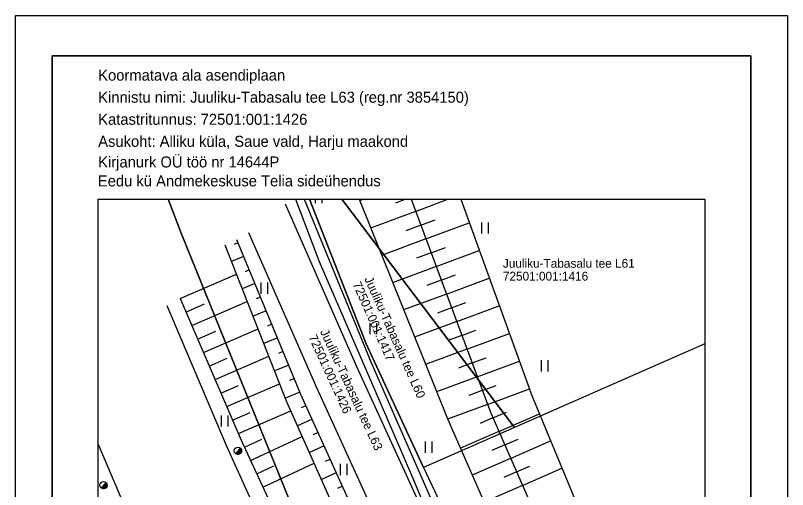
# Model space of a CAD drawing. Extents: x 533290.5 to 533343, y 6581488.2 to 6581562.4.
# Drawn here: x 533290.5 to 533343, y 6581530.2 to 6581562.4 of the extents above; entities that cross this region are included whole.
import ezdxf

# ---------------------------------------------------------------- set-up
doc = ezdxf.new("R2010")
doc.units = 0
for name, color, linetype in [('HALJASTUS', 7, 'Continuous'), ('MPKAABEL', 7, 'Continuous'), ('PIIR', 7, 'Continuous'), ('POST', 7, 'Continuous'), ('RELJEEF', 7, 'Continuous'), ('SITRASS', 7, 'Continuous'), ('TEE', 7, 'Continuous'), ('VORMISTUS', 7, 'Continuous')]:
    doc.layers.add(name, color=color, linetype=linetype)

msp = doc.modelspace()

# ---------------------------------------------------------------- linework, layer by layer
at = {"layer": 'HALJASTUS'}
for p, q in [((533310.914, 6581549.925), (533310.914, 6581549.665)), ((533311.369, 6581549.925), (533311.369, 6581549.665)), ((533322.224, 6581548.356), (533322.224, 6581547.595)), ((533322.679, 6581548.356), (533322.679, 6581547.595)), ((533307.211, 6581544.271), (533307.211, 6581543.51)), ((533307.666, 6581544.271), (533307.666, 6581543.51)), ((533314.628, 6581541.515), (533314.628, 6581540.754)), ((533315.083, 6581541.515), (533315.083, 6581540.754)), ((533326.275, 6581538.982), (533326.275, 6581538.221)), ((533326.73, 6581538.982), (533326.73, 6581538.221)), ((533304.51, 6581535.234), (533304.51, 6581534.473)), ((533304.966, 6581535.234), (533304.966, 6581534.473)), ((533318.384, 6581533.45), (533318.384, 6581532.689)), ((533318.839, 6581533.45), (533318.839, 6581532.689)), ((533312.613, 6581531.94), (533312.613, 6581531.179)), ((533313.068, 6581531.94), (533313.068, 6581531.179))]:
    msp.add_line(p, q, dxfattribs=at)
at = {"layer": 'MPKAABEL'}
msp.add_lwpolyline([(533309.585, 6581549.925), (533311.184, 6581545.697), (533315.768, 6581535.104), (533317.532, 6581531.021), (533318.413, 6581528.914), (533322.317, 6581520.59), (533323.335, 6581518.773), (533327.821, 6581509.555), (533328.223, 6581508.944), (533328.79, 6581508.605), (533328.705, 6581507.998), (533329.72, 6581506.331), (533333.034, 6581500.482)], dxfattribs=at)
at = {"layer": 'PIIR'}
for points in [[(533324.524, 6581497.425), (533319, 6581507.54), (533311.52, 6581523.65), (533301.8, 6581547.63), (533300.925, 6581549.925)], [(533300.925, 6581549.925), (533301.8, 6581547.63), (533311.52, 6581523.65), (533319, 6581507.54), (533324.524, 6581497.425)], [(533312.733, 6581549.925), (533324.47, 6581534.41), (533318.28, 6581531.69), (533314.39, 6581540.11), (533310.517, 6581549.925)], [(533310.517, 6581549.925), (533314.39, 6581540.11), (533318.28, 6581531.69), (533326.26, 6581514.77), (533336.001, 6581497.425)], [(533337.407, 6581540.101), (533324.47, 6581534.41), (533312.733, 6581549.925)], [(533337.407, 6581540.101), (533324.47, 6581534.41), (533318.28, 6581531.69), (533326.26, 6581514.77), (533336.001, 6581497.425)]]:
    msp.add_lwpolyline(points, dxfattribs=at)
at = {"layer": 'POST'}
for p, q in [((533305.487, 6581532.643), (533305.84, 6581532.997)), ((533296.35, 6581530.309), (533296.704, 6581530.663))]:
    msp.add_line(p, q, dxfattribs=at)
for centre in [(533305.664, 6581532.82), (533296.527, 6581530.486)]:
    msp.add_circle(centre, 0.25, dxfattribs=at)
for centre, radius, start, end in [((533305.664, 6581532.82), 0.225, 224.8541, 45.0356), ((533305.664, 6581532.82), 0.2, 224.8427, 45.047), ((533305.664, 6581532.82), 0.175, 224.8281, 45.0616), ((533305.664, 6581532.82), 0.15, 224.8087, 45.081), ((533305.664, 6581532.82), 0.125, 224.7814, 45.1083), ((533305.664, 6581532.82), 0.1, 224.7406, 45.1491), ((533305.664, 6581532.82), 0.075, 224.6725, 45.2172), ((533305.664, 6581532.82), 0.05, 224.5363, 45.3534), ((533305.664, 6581532.82), 0.025, 224.1278, 45.7619), ((533296.527, 6581530.486), 0.225, 224.8541, 45.0356), ((533296.527, 6581530.486), 0.2, 224.8427, 45.047), ((533296.527, 6581530.486), 0.175, 224.8281, 45.0616), ((533296.527, 6581530.486), 0.15, 224.8087, 45.081), ((533296.527, 6581530.486), 0.125, 224.7814, 45.1083), ((533296.527, 6581530.486), 0.1, 224.7406, 45.1491), ((533296.527, 6581530.486), 0.075, 224.6725, 45.2172), ((533296.527, 6581530.486), 0.05, 224.5363, 45.3534), ((533296.527, 6581530.486), 0.025, 224.1278, 45.7619)]:
    msp.add_arc(centre, radius, start, end, dxfattribs=at)
at = {"layer": 'RELJEEF'}
for p, q in [((533314.207, 6581549.925), (533313.935, 6581549.824)), ((533317.074, 6581549.925), (533316.367, 6581549.662)), ((533317.744, 6581549.107), (533319.942, 6581549.925)), ((533317.744, 6581549.107), (533314.683, 6581547.968)), ((533318.093, 6581548.17), (533317.081, 6581547.793)), ((533318.093, 6581548.17), (533319.079, 6581548.537)), ((533318.442, 6581547.233), (533321.391, 6581548.33)), ((533318.442, 6581547.233), (533315.43, 6581546.112)), ((533305.664, 6581546.968), (533305.395, 6581546.856)), ((533318.79, 6581546.296), (533319.771, 6581546.66)), ((533306.047, 6581546.044), (533305.223, 6581545.702)), ((533318.79, 6581546.296), (533317.795, 6581545.925)), ((533319.139, 6581545.358), (533322.072, 6581546.449)), ((533306.43, 6581545.12), (533306.15, 6581545.004)), ((533319.139, 6581545.358), (533316.178, 6581544.257)), ((533301.723, 6581543.178), (533305.563, 6581544.838)), ((533319.488, 6581544.421), (533318.509, 6581544.057)), ((533319.488, 6581544.421), (533320.463, 6581544.784)), ((533319.837, 6581543.484), (533322.753, 6581544.569)), ((533306.813, 6581544.197), (533305.955, 6581543.841)), ((533319.837, 6581543.484), (533316.925, 6581542.401)), ((533302.12, 6581542.26), (533303.39, 6581542.809)), ((533302.517, 6581541.343), (533306.295, 6581542.976)), ((533307.196, 6581543.273), (533306.905, 6581543.152)), ((533320.185, 6581542.547), (533321.155, 6581542.907)), ((533307.579, 6581542.349), (533306.687, 6581541.979)), ((533320.185, 6581542.547), (533319.223, 6581542.189)), ((533320.534, 6581541.609), (533323.434, 6581542.688)), ((533307.963, 6581541.426), (533307.66, 6581541.3)), ((533320.534, 6581541.609), (533317.673, 6581540.545)), ((533302.914, 6581540.425), (533304.163, 6581540.965)), ((533303.31, 6581539.507), (533307.028, 6581541.114)), ((533320.883, 6581540.672), (533321.847, 6581541.031)), ((533321.231, 6581539.735), (533324.115, 6581540.808)), ((533308.346, 6581540.502), (533307.42, 6581540.118)), ((533320.883, 6581540.672), (533319.937, 6581540.32)), ((533321.231, 6581539.735), (533318.42, 6581538.689)), ((533304.104, 6581537.671), (533307.761, 6581539.251)), ((533308.729, 6581539.578), (533308.414, 6581539.448)), ((533321.58, 6581538.798), (533322.539, 6581539.154)), ((533303.707, 6581538.589), (533304.936, 6581539.12)), ((533309.112, 6581538.654), (533308.152, 6581538.256)), ((533321.58, 6581538.798), (533320.651, 6581538.452)), ((533321.929, 6581537.86), (533324.796, 6581538.927)), ((533309.495, 6581537.731), (533309.169, 6581537.596)), ((533321.929, 6581537.86), (533319.168, 6581536.833)), ((533304.5, 6581536.753), (533305.709, 6581537.275)), ((533304.897, 6581535.835), (533308.493, 6581537.389)), ((533322.277, 6581536.923), (533323.23, 6581537.278)), ((533322.626, 6581535.986), (533325.477, 6581537.047)), ((533309.878, 6581536.807), (533308.884, 6581536.395)), ((533322.277, 6581536.923), (533321.365, 6581536.584)), ((533322.626, 6581535.986), (533319.915, 6581534.977)), ((533305.691, 6581533.999), (533309.257, 6581535.54)), ((533310.286, 6581535.894), (533309.957, 6581535.745)), ((533322.998, 6581535.058), (533323.923, 6581535.464)), ((533305.294, 6581534.917), (533306.482, 6581535.431)), ((533310.698, 6581534.983), (533309.707, 6581534.534)), ((533322.998, 6581535.058), (533322.126, 6581534.676)), ((533323.399, 6581534.142), (533326.157, 6581535.351)), ((533311.111, 6581534.072), (533310.779, 6581533.922)), ((533323.399, 6581534.142), (533320.785, 6581532.996)), ((533306.099, 6581533.086), (533307.275, 6581533.629)), ((533306.518, 6581532.179), (533310.034, 6581533.802)), ((533323.801, 6581533.226), (533324.714, 6581533.627)), ((533324.202, 6581532.31), (533326.923, 6581533.503)), ((533311.523, 6581533.161), (533310.523, 6581532.708)), ((533323.801, 6581533.226), (533322.93, 6581532.844)), ((533324.202, 6581532.31), (533321.59, 6581531.165)), ((533306.938, 6581531.271), (533308.106, 6581531.81)), ((533307.357, 6581530.363), (533310.85, 6581531.976)), ((533311.936, 6581532.25), (533311.601, 6581532.099)), ((533324.604, 6581531.395), (533325.505, 6581531.79)), ((533312.348, 6581531.339), (533311.34, 6581530.883)), ((533324.604, 6581531.395), (533323.733, 6581531.013)), ((533325.005, 6581530.479), (533327.69, 6581531.656)), ((533312.761, 6581530.428), (533312.423, 6581530.275)), ((533325.005, 6581530.479), (533322.395, 6581529.334))]:
    msp.add_line(p, q, dxfattribs=at)
for points in [[(533313.894, 6581549.925), (533319.924, 6581534.957), (533327.024, 6581518.802), (533337.222, 6581500.851)], [(533317.44, 6581549.925), (533322.824, 6581535.454), (533329.77, 6581519.61), (533337.407, 6581506.072)], [(533320.813, 6581549.925), (533325.642, 6581536.592), (533332.201, 6581520.786), (533337.407, 6581512.283)], [(533301.723, 6581543.178), (533305.883, 6581533.554), (533310.992, 6581522.492), (533312.743, 6581519.341), (533315.111, 6581515.828), (533317.088, 6581516.41), (533318.52, 6581517.115), (533318.885, 6581518.236), (533315.236, 6581524.96), (533309.937, 6581536.665), (533305.583, 6581547.162)], [(533317.816, 6581517.779), (533314.186, 6581524.519), (533308.956, 6581536.213), (533304.785, 6581546.815)]]:
    msp.add_lwpolyline(points, dxfattribs=at)
at = {"layer": 'SITRASS'}
msp.add_lwpolyline([(533310.167, 6581549.925), (533314.701, 6581538.877), (533321.41, 6581523.582), (533328.373, 6581509.225), (533329.36, 6581508.341), (533331.911, 6581502.769), (533333.333, 6581500.509)], dxfattribs=at)
at = {"layer": 'TEE'}
for points in [[(533332.365, 6581500.423), (533328.37, 6581507.695), (533323.599, 6581517.205), (533319.091, 6581526.86), (533313.759, 6581538.502), (533308.885, 6581549.596)], [(533300.834, 6581542.715), (533304.915, 6581533.103), (533309.953, 6581521.952), (533312.545, 6581516.498), (533313.78, 6581513.945), (533314.812, 6581514.331), (533318.385, 6581515.808), (533320.487, 6581516.887), (533319.399, 6581519.093), (533316.302, 6581525.558), (533311.019, 6581537.113), (533306.407, 6581547.637)], [(533296.157, 6581522.88), (533296.727, 6581523.417), (533297.752, 6581526.189), (533298.149, 6581528.6), (533296.157, 6581533.295)]]:
    msp.add_lwpolyline(points, dxfattribs=at)
at = {"layer": 'VORMISTUS'}
for points in [[(533290.532, 6581562.425), (533343.032, 6581562.425), (533343.032, 6581488.175), (533290.532, 6581488.175)], [(533293.032, 6581490.925), (533340.532, 6581490.925), (533340.532, 6581559.675), (533293.032, 6581559.675)], [(533293.032, 6581559.675), (533340.532, 6581559.675), (533340.532, 6581490.925), (533293.032, 6581490.925)], [(533337.407, 6581497.425), (533296.157, 6581497.425), (533296.157, 6581549.925), (533337.407, 6581549.925)]]:
    msp.add_lwpolyline(points, close=True, dxfattribs=at)

# ---------------------------------------------------------------- texts
at = {"layer": 'PIIR'}
for s, p in [('Juuliku-Tabasalu tee L61', (533323.675, 6581545.274)), ('72501:001:1416', (533323.675, 6581544.399))]:
    msp.add_text(s, height=0.6, dxfattribs=at).set_placement(p)
for s, rotation, p in [('Juuliku-Tabasalu tee L60', 293.9907, (533314.242, 6581544.521)), ('72501:001:1417', 293.9907, (533313.443, 6581544.165)), ('72501:001:1426', 294.7546, (533310.441, 6581540.558)), ('Juuliku-Tabasalu tee L63', 294.7546, (533311.235, 6581540.925))]:
    msp.add_text(s, height=0.6, rotation=rotation, dxfattribs=at).set_placement(p)
at = {"layer": 'VORMISTUS'}
for s, p in [('Koormatava ala asendiplaan', (533296.16, 6581557.992)), ('Kinnistu nimi: Juuliku-Tabasalu tee L63 (reg.nr 3854150)', (533296.16, 6581556.492)), ('Katastritunnus: 72501:001:1426', (533296.16, 6581554.992)), ('Asukoht: Alliku küla, Saue vald, Harju maakond', (533296.16, 6581553.492))]:
    msp.add_text(s, height=0.75, dxfattribs=at).set_placement(p)
for s, p in [('Kirjanurk OÜ töö nr 14644P', (533296.156, 6581552.09)), ('Eedu kü Andmekeskuse Telia sideühendus', (533296.137, 6581550.803))]:
    msp.add_text(s, height=0.75, rotation=360, dxfattribs=at).set_placement(p)

doc.saveas('drawing.dxf')
